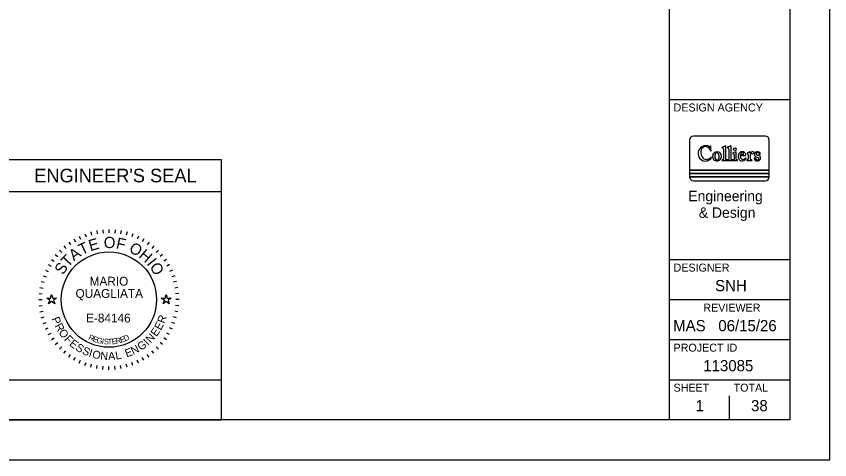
# Model space of a CAD drawing. Extents: x 0 to 39.4, y 0 to 22.
# Drawn here: x 23.84 to 34, y 0 to 5.54 of the extents above; entities that cross this region are included whole.
import ezdxf

# ---------------------------------------------------------------- set-up
doc = ezdxf.new("R2010")
doc.units = 0
for name, color, linetype in [('SH_Border', 7, 'Continuous'), ('SH_Cut_Line', 7, 'Continuous'), ('SH_Data', 7, 'Continuous'), ('SH_Seal', 7, 'Continuous'), ('SH_Text', 7, 'Continuous')]:
    doc.layers.add(name, color=color, linetype=linetype)

msp = doc.modelspace()

# ---------------------------------------------------------------- linework, layer by layer
at = {"layer": 'SH_Border'}
for p, q in [((32, 0.5), (32, 21.5)), ((32, 4.5), (33.5, 4.5)), ((32, 2.5), (33.5, 2.5)), ((32, 2), (33.5, 2)), ((32, 1.5), (33.5, 1.5)), ((32, 1), (33.5, 1))]:
    msp.add_line(p, q, dxfattribs=at)
msp.add_lwpolyline([(1.5, 21.5), (33.5, 21.5), (33.5, 0.5), (1.5, 0.5)], close=True, dxfattribs=at)
at = {"layer": 'SH_Cut_Line'}
msp.add_lwpolyline([(0, 0), (34, 0), (34, 22), (0, 22)], close=True, dxfattribs=at)
at = {"layer": 'SH_Data'}
for p, q in [((23.6, 3.75), (26.4, 3.75)), ((26.4, 3.75), (26.4, 0.5)), ((32.75, 3.5), (32.75, 3.5)), ((23.6, 3.35), (26.4, 3.35)), ((32.75, 0.5), (32.75, 0.8)), ((32.375, 0.675), (32.375, 0.675)), ((23.6, 0.5), (26.4, 0.5))]:
    msp.add_line(p, q, dxfattribs=at)
msp.add_lwpolyline([(23.6, 0.5), (23.6, 1), (26.4, 1), (26.4, 0.5)], close=True, dxfattribs=at)
at = {"layer": 'SH_Seal'}
for p, q in [((24.774, 2.845), (24.784, 2.807)), ((24.848, 2.862), (24.855, 2.822)), ((24.924, 2.872), (24.927, 2.832)), ((25, 2.875), (25, 2.835)), ((25.076, 2.872), (25.073, 2.832)), ((25.152, 2.862), (25.145, 2.822)), ((25.226, 2.845), (25.216, 2.807)), ((24.563, 2.758), (24.583, 2.723)), ((24.63, 2.793), (24.647, 2.757)), ((24.701, 2.822), (24.714, 2.785)), ((25.299, 2.822), (25.286, 2.785)), ((25.37, 2.793), (25.353, 2.757)), ((25.437, 2.758), (25.417, 2.723)), ((24.438, 2.67), (24.463, 2.64)), ((24.498, 2.717), (24.521, 2.684)), ((25.502, 2.717), (25.479, 2.684)), ((25.562, 2.67), (25.537, 2.64)), ((24.33, 2.562), (24.36, 2.537)), ((24.381, 2.619), (24.41, 2.59)), ((25.619, 2.619), (25.59, 2.59)), ((25.67, 2.562), (25.64, 2.537)), ((24.283, 2.502), (24.316, 2.479)), ((25.717, 2.502), (25.684, 2.479)), ((24.207, 2.37), (24.243, 2.353)), ((24.242, 2.438), (24.277, 2.418)), ((25.758, 2.438), (25.723, 2.418)), ((25.793, 2.37), (25.757, 2.353)), ((24.178, 2.299), (24.215, 2.286)), ((25.822, 2.299), (25.785, 2.286)), ((24.138, 2.152), (24.178, 2.145)), ((24.155, 2.226), (24.193, 2.216)), ((25.845, 2.226), (25.807, 2.216)), ((25.862, 2.152), (25.822, 2.145)), ((24.128, 2.076), (24.168, 2.073)), ((25.872, 2.076), (25.832, 2.073)), ((24.125, 2), (24.165, 2)), ((25.875, 2), (25.835, 2)), ((24.128, 1.924), (24.168, 1.927)), ((24.138, 1.848), (24.178, 1.855)), ((25.862, 1.848), (25.822, 1.855)), ((25.872, 1.924), (25.832, 1.927)), ((24.155, 1.774), (24.193, 1.784)), ((25.845, 1.774), (25.807, 1.784)), ((24.178, 1.701), (24.215, 1.714)), ((24.207, 1.63), (24.243, 1.647)), ((25.793, 1.63), (25.757, 1.647)), ((25.822, 1.701), (25.785, 1.714)), ((24.242, 1.563), (24.277, 1.583)), ((25.758, 1.563), (25.723, 1.583)), ((24.283, 1.498), (24.316, 1.521)), ((24.33, 1.438), (24.36, 1.463)), ((25.67, 1.438), (25.64, 1.463)), ((25.717, 1.498), (25.684, 1.521)), ((24.381, 1.381), (24.41, 1.41)), ((24.438, 1.33), (24.463, 1.36)), ((25.562, 1.33), (25.537, 1.36)), ((25.619, 1.381), (25.59, 1.41)), ((24.498, 1.283), (24.521, 1.316)), ((24.563, 1.242), (24.583, 1.277)), ((24.63, 1.207), (24.647, 1.243)), ((25.37, 1.207), (25.353, 1.243)), ((25.437, 1.242), (25.417, 1.277)), ((25.502, 1.283), (25.479, 1.316)), ((24.701, 1.178), (24.714, 1.215)), ((24.774, 1.155), (24.784, 1.193)), ((24.848, 1.138), (24.855, 1.178)), ((24.924, 1.128), (24.927, 1.168)), ((25, 1.125), (25, 1.165)), ((25.076, 1.128), (25.073, 1.168)), ((25.152, 1.138), (25.145, 1.178)), ((25.226, 1.155), (25.216, 1.193)), ((25.299, 1.178), (25.286, 1.215))]:
    msp.add_line(p, q, dxfattribs=at)
for points in [[(24.224, 2.02), (24.271, 2.02), (24.285, 2.065), (24.299, 2.02), (24.346, 2.02), (24.308, 1.992), (24.323, 1.948), (24.285, 1.975), (24.247, 1.948), (24.262, 1.992)], [(25.654, 2.02), (25.701, 2.02), (25.715, 2.065), (25.729, 2.02), (25.776, 2.02), (25.738, 1.992), (25.753, 1.948), (25.715, 1.975), (25.677, 1.948), (25.692, 1.992)]]:
    msp.add_lwpolyline(points, close=True, dxfattribs=at)
msp.add_circle((25, 2), 0.595, dxfattribs=at)
at = {"layer": 'SH_Text'}
for p, q in [((33.195, 4.043), (32.299, 4.043)), ((32.506, 3.913), (32.507, 3.91)), ((32.511, 3.864), (32.513, 3.859)), ((32.674, 3.881), (32.674, 3.753)), ((32.701, 3.752), (32.701, 3.916)), ((32.741, 3.879), (32.741, 3.751)), ((32.768, 3.751), (32.768, 3.916)), ((32.518, 3.765), (32.522, 3.77)), ((32.596, 3.846), (32.59, 3.846)), ((32.827, 3.846), (32.791, 3.832)), ((32.805, 3.812), (32.805, 3.751)), ((32.832, 3.749), (32.832, 3.843)), ((32.886, 3.802), (32.947, 3.802)), ((32.919, 3.81), (32.887, 3.81)), ((33, 3.846), (32.969, 3.831)), ((32.969, 3.825), (32.976, 3.821)), ((32.982, 3.81), (32.982, 3.753)), ((33.007, 3.828), (33.006, 3.843)), ((33.01, 3.753), (33.01, 3.807)), ((33.11, 3.833), (33.125, 3.816)), ((33.132, 3.82), (33.13, 3.835)), ((32.667, 3.745), (32.658, 3.745)), ((32.658, 3.737), (32.845, 3.737)), ((32.734, 3.745), (32.707, 3.745)), ((32.799, 3.745), (32.774, 3.745)), ((32.845, 3.745), (32.836, 3.745)), ((32.975, 3.745), (32.968, 3.745)), ((32.968, 3.737), (33.026, 3.737)), ((33.026, 3.745), (33.017, 3.745)), ((33.245, 3.535), (33.245, 3.575)), ((32.249, 3.533), (33.244, 3.533)), ((33.244, 3.533), (32.249, 3.533)), ((32.299, 3.485), (33.195, 3.485))]:
    msp.add_line(p, q, dxfattribs=at)
for points in [[(32.249, 3.993), (32.249, 3.617), (33.245, 3.617), (33.245, 3.993)], [(32.521, 3.861), (32.516, 3.886), (32.514, 3.914)], [(33.245, 3.575), (32.249, 3.575), (32.249, 3.535)]]:
    msp.add_lwpolyline(points, dxfattribs=at)
msp.add_lwpolyline([(33.245, 3.617), (32.249, 3.617), (32.249, 3.575), (33.245, 3.575)], close=True, dxfattribs=at)
msp.add_circle((32.815, 3.879), 0.0155, dxfattribs=at)
for centre, radius, start, end in [((32.299, 3.993), 0.0498, 90, 180), ((33.195, 3.993), 0.0498, 0, 90), ((32.456, 3.826), 0.0996, 122.7772, 219.4331), ((32.457, 3.848), 0.0652, 110.6135, 175.9543), ((32.45, 3.835), 0.0884, 54.7696, 122.7772), ((32.45, 3.867), 0.0454, 67.8997, 110.6135), ((32.437, 3.835), 0.0794, 21.2674, 67.8997), ((32.503, 3.91), 0.00381, 234.7696, 0.2433), ((32.51, 3.914), 0.00392, 10.93, 183.8175), ((32.516, 3.862), 0.00427, 213.048, 354.7379), ((32.657, 3.901), 0.00323, 122.5943, 271.3615), ((32.544, 4.221), 0.336, 289.2258, 296.5694), ((32.657, 3.881), 0.0166, 0, 91.3615), ((32.696, 3.916), 0.00466, 0.7043, 112.8976), ((32.724, 3.902), 0.00377, 108.5217, 257.147), ((32.641, 4.168), 0.275, 287.2899, 295.7863), ((32.722, 3.879), 0.019, 0, 85.065), ((32.763, 3.916), 0.00504, 3.9002, 114.2106), ((32.445, 3.817), 0.0857, 219.4331, 285.3506), ((32.526, 3.843), 0.135, 175.9543, 206.5569), ((32.458, 3.81), 0.059, 206.5569, 271.2175), ((32.458, 3.828), 0.0773, 271.2175, 317.7042), ((32.44, 3.834), 0.104, 285.3506, 318.3029), ((32.518, 3.773), 0.00456, 317.5815, 137.7042), ((32.594, 3.79), 0.0573, 155.0154, 195.9836), ((32.593, 3.79), 0.0568, 195.9836, 247.4134), ((32.591, 3.791), 0.0549, 91.4708, 155.0154), ((32.627, 3.79), 0.0628, 159.8672, 197.1421), ((32.617, 3.787), 0.0527, 197.1421, 229.9048), ((32.613, 3.795), 0.0485, 128.4847, 159.8672), ((32.592, 3.822), 0.0143, 51.5153, 128.4847), ((32.596, 3.791), 0.0547, 22.5432, 90), ((32.572, 3.797), 0.0457, 8.6045, 51.5153), ((32.573, 3.782), 0.0463, 311.5123, 356.3189), ((32.586, 3.797), 0.0652, 292.5866, 340.2533), ((32.532, 3.787), 0.0872, 354.2931, 11.1311), ((32.599, 3.792), 0.0508, 340.2533, 22.5432), ((32.794, 3.829), 0.00399, 126.9098, 263.7558), ((32.792, 3.812), 0.0128, 0, 83.7558), ((32.829, 3.843), 0.00324, 356.2318, 111.3032), ((32.936, 3.789), 0.0786, 158.9201, 196.7689), ((32.904, 3.78), 0.0455, 196.7689, 259.4625), ((32.906, 3.801), 0.0468, 107.3884, 158.9201), ((32.928, 3.794), 0.0459, 174.8749, 230.9242), ((32.886, 3.798), 0.00367, 90, 174.8749), ((32.917, 3.807), 0.0332, 120.4846, 167.2691), ((32.887, 3.813), 0.00338, 167.2691, 270), ((32.909, 3.792), 0.0557, 72.6116, 107.3884), ((32.906, 3.79), 0.0563, 259.4625, 329.9587), ((32.92, 3.784), 0.0321, 230.9242, 328.1623), ((32.907, 3.823), 0.0144, 42.3189, 120.4846), ((32.901, 3.817), 0.0231, 354.1231, 42.3189), ((32.918, 3.815), 0.00543, 277.2594, 354.1231), ((32.914, 3.809), 0.0381, 357.2625, 72.6116), ((32.946, 3.807), 0.00555, 272.7564, 357.2625), ((32.951, 3.764), 0.00454, 329.9587, 148.1623), ((32.971, 3.828), 0.0034, 121.2415, 241.2505), ((32.969, 3.81), 0.0136, 0, 59.7444), ((33.002, 3.843), 0.00375, 6.4513, 116.174), ((33.009, 3.828), 0.00158, 185.3907, 323.4477), ((33.094, 3.765), 0.104, 130.2856, 143.4477), ((33.033, 3.807), 0.0235, 141.4263, 180.0327), ((33.023, 3.815), 0.0105, 58.8554, 141.4263), ((33.038, 3.831), 0.0179, 49.7144, 130.2856), ((33.038, 3.839), 0.018, 238.8554, 310.2856), ((33.041, 3.835), 0.0124, 310.2856, 49.7144), ((33.093, 3.812), 0.0332, 143.4089, 199.3264), ((33.065, 3.768), 0.00485, 20.4198, 193.2731), ((32.948, 3.74), 0.116, 4.8826, 13.2731), ((33.087, 3.81), 0.0263, 199.3264, 242.7351), ((33.093, 3.812), 0.0334, 105.6066, 143.4089), ((33.118, 3.787), 0.0516, 200.4198, 231.7135), ((33.141, 3.915), 0.144, 242.7351, 255.1442), ((33.093, 3.822), 0.0133, 123.6114, 236.3886), ((33.099, 3.79), 0.0558, 61.5074, 105.6066), ((33.099, 3.813), 0.0238, 78.1441, 123.6114), ((33.111, 3.85), 0.0468, 236.3886, 262.0524), ((33.101, 3.825), 0.0115, 42.5173, 78.1441), ((33.1, 3.76), 0.016, 325.4966, 75.1442), ((33.099, 3.763), 0.0407, 40.9976, 82.0524), ((33.128, 3.819), 0.00433, 219.7222, 9.1323), ((33.122, 3.833), 0.00795, 16.8946, 61.5074), ((33.107, 3.77), 0.0305, 319.0024, 40.9976), ((32.591, 3.784), 0.0512, 247.4134, 292.5866), ((32.593, 3.759), 0.0157, 229.9048, 310.0952), ((32.658, 3.741), 0.00412, 90, 270), ((32.667, 3.752), 0.00695, 270, 7.6881), ((32.709, 3.752), 0.00806, 180, 256.9766), ((32.734, 3.751), 0.0065, 270, 3.1556), ((32.775, 3.751), 0.00652, 179.2506, 264.6402), ((32.799, 3.75), 0.00532, 270, 12.3402), ((32.837, 3.749), 0.00485, 180, 266.7746), ((32.845, 3.741), 0.00381, 270, 90), ((32.968, 3.741), 0.00381, 91.0116, 270), ((32.975, 3.752), 0.00704, 270, 9.7141), ((33.018, 3.752), 0.00796, 179.3196, 263.9925), ((33.026, 3.741), 0.00381, 270, 90), ((33.077, 3.751), 0.014, 184.8826, 242.2064), ((33.093, 3.782), 0.0486, 242.2064, 319.0024), ((33.098, 3.761), 0.0185, 231.7135, 325.4966), ((32.299, 3.535), 0.0498, 180, 183.1495), ((32.299, 3.535), 0.0498, 183.1495, 270), ((33.195, 3.535), 0.0498, 270, 356.8505), ((33.195, 3.535), 0.0498, 356.8505, 0)]:
    msp.add_arc(centre, radius, start, end, dxfattribs=at)

# ---------------------------------------------------------------- texts
at = {"layer": 'SH_Data'}
for s, height, p in [('DESIGN AGENCY', 0.1, (32.05, 4.35)), ("ENGINEER'S SEAL", 0.17, (24.068, 3.465)), ('DESIGNER', 0.1, (32.05, 2.35)), ('SNH', 0.14, (32.569, 2.105)), ('REVIEWER', 0.1, (32.422, 1.85)), ('MAS', 0.14, (32.045, 1.605)), ('06/15/26', 0.14, (32.609, 1.605)), ('PROJECT ID', 0.1, (32.05, 1.35)), ('113085', 0.14, (32.421, 1.105)), ('SHEET', 0.1, (32.05, 0.85)), ('TOTAL', 0.1, (32.8, 0.85)), ('1', 0.14, (32.325, 0.605)), ('38', 0.14, (33.018, 0.605))]:
    msp.add_text(s, height=height, dxfattribs=at).set_placement(p)
at = {"layer": 'SH_Seal'}
for s, height, rotation, p in [('E', 0.14, 15.7571, (24.768, 2.604)), ('O', 0.14, 359.7812, (24.935, 2.644)), ('F', 0.14, 347.4362, (25.081, 2.642)), ('T', 0.14, 25.7167, (24.662, 2.552)), ('O', 0.14, 332.2586, (25.24, 2.602)), ('T', 0.14, 46.4344, (24.488, 2.396)), ('A', 0.14, 36.4747, (24.563, 2.478)), ('H', 0.14, 319.9136, (25.363, 2.536)), ('S', 0.14, 57.1924, (24.428, 2.301)), ('I', 0.14, 308.367, (25.466, 2.448)), ('O', 0.14, 303.1491, (25.502, 2.409)), ('P', 0.1, 291.494, (24.282, 1.762)), ('E', 0.1, 61.9951, (25.648, 1.61)), ('R', 0.1, 69.2322, (25.692, 1.695)), ('R', 0.1, 298.7311, (24.319, 1.672)), ('O', 0.1, 306.4666, (24.365, 1.588)), ('E', 0.1, 54.758, (25.593, 1.531)), ('F', 0.1, 314.7068, (24.434, 1.498)), ('R', 0.07, 334.487, (24.737, 1.505)), ('E', 0.07, 341.04, (24.791, 1.48)), ('G', 0.07, 347.4752, (24.841, 1.462)), ('R', 0.07, 11.9184, (25.092, 1.447)), ('E', 0.07, 17.6836, (25.15, 1.46)), ('D', 0.07, 23.3052, (25.201, 1.477)), ('N', 0.1, 47.0224, (25.52, 1.451)), ('E', 0.1, 321.4393, (24.498, 1.435)), ('S', 0.1, 328.6764, (24.574, 1.375)), ('I', 0.07, 353.7858, (24.909, 1.447)), ('S', 0.07, 356.8926, (24.936, 1.443)), ('T', 0.07, 3.0061, (24.986, 1.439)), ('E', 0.07, 6.0117, (25.039, 1.441)), ('N', 0.1, 27.3113, (25.304, 1.308)), ('G', 0.1, 35.0469, (25.398, 1.357)), ('I', 0.1, 43.287, (25.487, 1.421)), ('S', 0.1, 335.9134, (24.656, 1.327)), ('I', 0.1, 343.1505, (24.741, 1.29)), ('O', 0.1, 346.8859, (24.784, 1.275)), ('N', 0.1, 355.1261, (24.889, 1.252)), ('A', 0.1, 2.8617, (24.992, 1.244)), ('L', 0.1, 10.0987, (25.089, 1.249)), ('E', 0.1, 20.0742, (25.221, 1.277))]:
    msp.add_text(s, height=height, rotation=rotation, dxfattribs=at).set_placement(p)
for s, p in [('MARIO', (24.759, 2.175)), ('QUAGLIATA ', (24.583, 2.022)), ('E-84146', (24.715, 1.715))]:
    msp.add_text(s, height=0.11, dxfattribs=at).set_placement(p)
at = {"layer": 'SH_Text'}
for s, height, p in [('Engineering', 0.13025, (32.234, 3.229)), ('& Design', 0.1303, (32.365, 3.022))]:
    msp.add_text(s, height=height, dxfattribs=at).set_placement(p)

doc.saveas('drawing.dxf')
